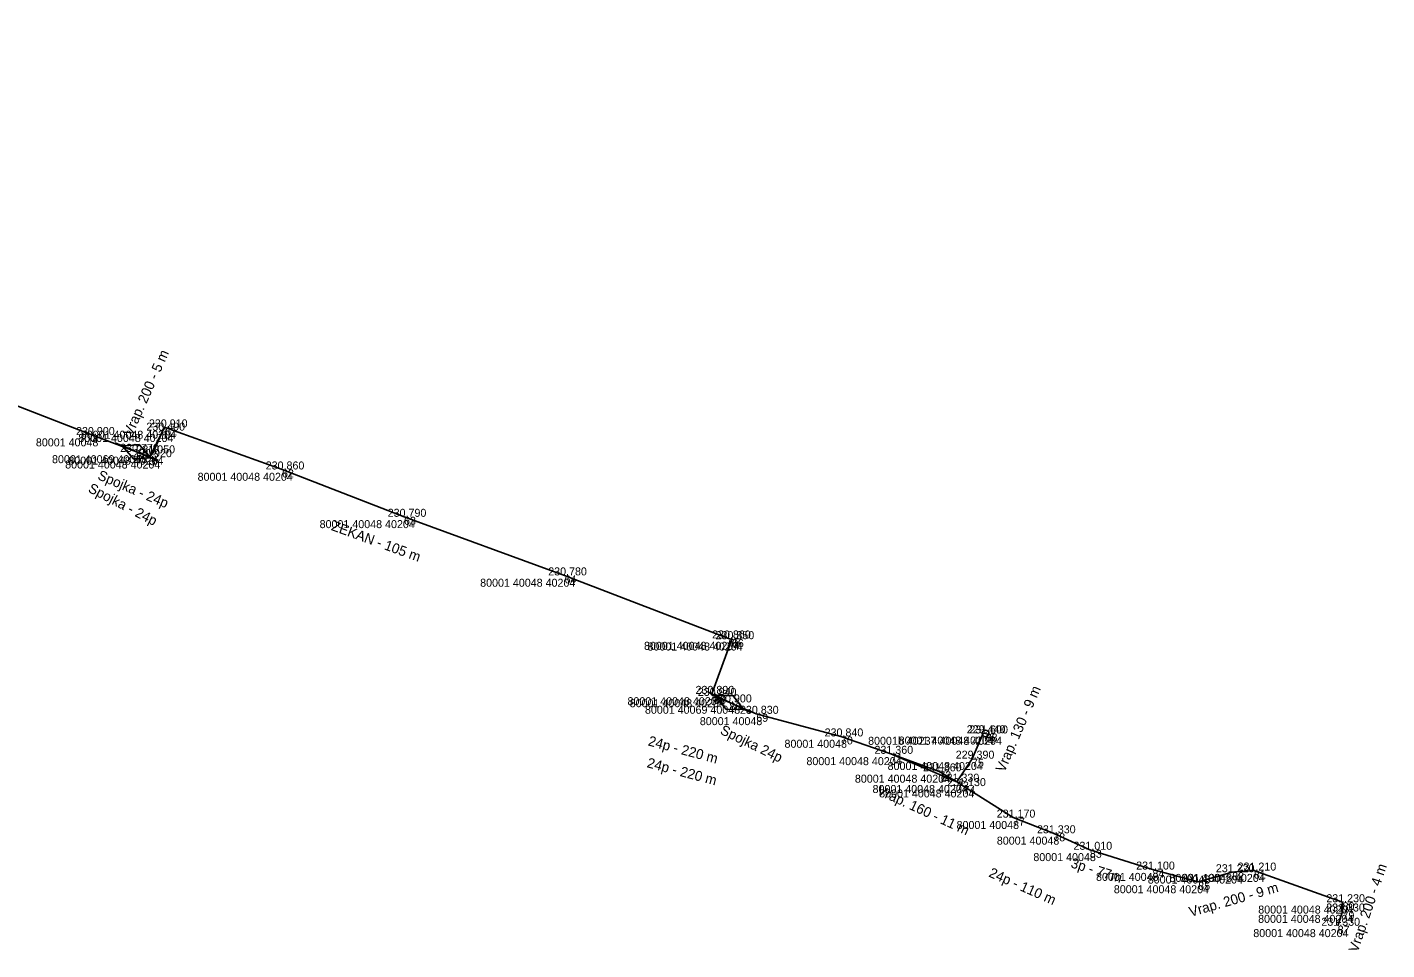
# Model space of a CAD drawing. Extents: x -771675 to -771031, y -1050148 to -1049817.
# Drawn here: x -771234.6 to -771030.6, y -1050147.5 to -1050009.1 of the extents above; entities that cross this region are included whole.
import ezdxf

# ---------------------------------------------------------------- set-up
doc = ezdxf.new("R2010")
doc.units = 0
for name, color, linetype in [('Vrstva 27', 7, 'Continuous'), ('Vrstva 28', 7, 'Continuous'), ('Vrstva 35', 7, 'Continuous'), ('Vrstva 60', 7, 'Continuous'), ('Vrstva 61', 7, 'Continuous'), ('Vrstva 62', 7, 'Continuous')]:
    doc.layers.add(name, color=color, linetype=linetype)

msp = doc.modelspace()

# ---------------------------------------------------------------- linework, layer by layer
at = {"layer": 'Vrstva 27'}
msp.add_line((-771090.85, -1050115.04), (-771090.77, -1050115.1), dxfattribs=at)
msp.add_circle((-771090.81, -1050115.07), 0.5, dxfattribs=at)
at = {"layer": 'Vrstva 28'}
for p, q in [((-771214.92, -1050074.07), (-771221.44, -1050071.59)), ((-771214.92, -1050074.07), (-771221.44, -1050071.59)), ((-771214.97, -1050074.2), (-771221.39, -1050071.46)), ((-771220.35, -1050072), (-771217.77, -1050071.74)), ((-771220.35, -1050072), (-771217.77, -1050071.74)), ((-771218.59, -1050073.92), (-771220.35, -1050072)), ((-771218.59, -1050073.92), (-771220.35, -1050072)), ((-771220.32, -1050071.92), (-771217.72, -1050071.76)), ((-771218.64, -1050073.9), (-771220.32, -1050071.92)), ((-771217.77, -1050071.74), (-771216.01, -1050073.66)), ((-771217.77, -1050071.74), (-771216.01, -1050073.66)), ((-771217.72, -1050071.76), (-771216.04, -1050073.74)), ((-771216.04, -1050073.74), (-771218.64, -1050073.9)), ((-771216.01, -1050073.66), (-771218.59, -1050073.92)), ((-771216.01, -1050073.66), (-771218.59, -1050073.92)), ((-771126.1, -1050111.94), (-771132.38, -1050108.88)), ((-771131.33, -1050109.39), (-771128.73, -1050109.36)), ((-771129.75, -1050111.46), (-771131.33, -1050109.39)), ((-771128.73, -1050109.36), (-771127.15, -1050111.43)), ((-771127.15, -1050111.43), (-771129.75, -1050111.46))]:
    msp.add_line(p, q, dxfattribs=at)
for points in [[(-771381.07, -1050009.14), (-771379.8, -1050009.7), (-771371.17, -1050012.96), (-771358.66, -1050018.45), (-771346.42, -1050023.74), (-771329.39, -1050030.95), (-771327.8, -1050031.37), (-771308.34, -1050039.35), (-771281.13, -1050049.41), (-771278.57, -1050050.27), (-771268.38, -1050053.56), (-771265.96, -1050054.48), (-771239.24, -1050064.74), (-771224.8, -1050070.31), (-771218.18, -1050072.83)], [(-771239.24, -1050064.74), (-771224.8, -1050070.31), (-771218.18, -1050072.83), (-771216.22, -1050073.63), (-771215.75, -1050073.05), (-771214.25, -1050069.65), (-771213.87, -1050069.16), (-771196.35, -1050075.47), (-771178.05, -1050082.57), (-771153.97, -1050091.36), (-771129.39, -1050100.82), (-771128.87, -1050100.93), (-771131.87, -1050109.13), (-771131.54, -1050109.43), (-771129.24, -1050110.41), (-771125.21, -1050112.12), (-771112.51, -1050115.51), (-771105.03, -1050118.12), (-771097.76, -1050120.75), (-771095.11, -1050122.3), (-771094.12, -1050122.96), (-771086.7, -1050127.69), (-771080.66, -1050130.04), (-771075.18, -1050132.51), (-771065.78, -1050135.48), (-771058.92, -1050137.33), (-771053.83, -1050135.88), (-771050.57, -1050135.63), (-771037.26, -1050140.38), (-771037.28, -1050141.77), (-771038, -1050143.91)], [(-771129.24, -1050110.41), (-771131.54, -1050109.43), (-771131.87, -1050109.13), (-771128.87, -1050100.93), (-771129.39, -1050100.82), (-771153.97, -1050091.36), (-771178.05, -1050082.57), (-771196.35, -1050075.47), (-771213.87, -1050069.16), (-771214.25, -1050069.65), (-771215.75, -1050073.05), (-771216.22, -1050073.63), (-771218.18, -1050072.83), (-771224.8, -1050070.31), (-771239.24, -1050064.74)], [(-771218.18, -1050072.83), (-771216.22, -1050073.63), (-771215.75, -1050073.05), (-771214.25, -1050069.65), (-771213.87, -1050069.16), (-771196.35, -1050075.47), (-771178.05, -1050082.57), (-771153.97, -1050091.36), (-771129.39, -1050100.82), (-771128.87, -1050100.93), (-771131.87, -1050109.13), (-771131.54, -1050109.43), (-771129.24, -1050110.41)], [(-771218.18, -1050072.83), (-771216.22, -1050073.63), (-771214.25, -1050069.65), (-771213.87, -1050069.16), (-771196.35, -1050075.47), (-771178.05, -1050082.57), (-771153.97, -1050091.36), (-771129.39, -1050100.82), (-771128.87, -1050100.93), (-771131.87, -1050109.13), (-771131.54, -1050109.43), (-771129.24, -1050110.41), (-771125.21, -1050112.12), (-771112.51, -1050115.51), (-771105.03, -1050118.12), (-771097.76, -1050120.75), (-771095.11, -1050122.3), (-771094.12, -1050122.96), (-771086.7, -1050127.69), (-771080.66, -1050130.04), (-771075.18, -1050132.51), (-771065.78, -1050135.48), (-771058.92, -1050137.33), (-771053.83, -1050135.88), (-771050.57, -1050135.63), (-771037.26, -1050140.38), (-771037.28, -1050141.77), (-771038, -1050143.91)], [(-771038, -1050143.91), (-771037.28, -1050141.77), (-771037.26, -1050140.38), (-771050.57, -1050135.63), (-771053.83, -1050135.88), (-771058.92, -1050137.33), (-771065.78, -1050135.48), (-771075.18, -1050132.51), (-771080.66, -1050130.04), (-771086.7, -1050127.69), (-771094.12, -1050122.96), (-771095.11, -1050122.3), (-771105.03, -1050118.12), (-771112.51, -1050115.51), (-771125.21, -1050112.12), (-771129.24, -1050110.41), (-771131.54, -1050109.43), (-771131.87, -1050109.13), (-771128.87, -1050100.93), (-771129.39, -1050100.82), (-771153.97, -1050091.36), (-771178.05, -1050082.57), (-771196.35, -1050075.47), (-771213.87, -1050069.16), (-771214.25, -1050069.65), (-771215.75, -1050073.05), (-771216.22, -1050073.63), (-771218.18, -1050072.83)], [(-771038, -1050143.91), (-771037.28, -1050141.77), (-771037.26, -1050140.38), (-771050.57, -1050135.63), (-771053.83, -1050135.88), (-771058.92, -1050137.33), (-771065.78, -1050135.48), (-771075.18, -1050132.51), (-771080.66, -1050130.04), (-771086.7, -1050127.69), (-771094.12, -1050122.96), (-771095.11, -1050122.3), (-771097.76, -1050120.75), (-771105.03, -1050118.12), (-771112.51, -1050115.51), (-771125.21, -1050112.12), (-771129.24, -1050110.41)], [(-771038, -1050143.91), (-771037.28, -1050141.77), (-771037.26, -1050140.38), (-771050.57, -1050135.63), (-771053.83, -1050135.88), (-771058.92, -1050137.33), (-771065.78, -1050135.48), (-771075.18, -1050132.51), (-771080.66, -1050130.04), (-771086.7, -1050127.69), (-771094.12, -1050122.96), (-771095.11, -1050122.3), (-771092.85, -1050118.85), (-771091.19, -1050115.03), (-771090.81, -1050115.07)]]:
    msp.add_lwpolyline(points, dxfattribs=at)
at = {"layer": 'Vrstva 35'}
for points in [[(-771213.87, -1050069.16), (-771214.25, -1050069.65), (-771215.75, -1050073.05), (-771216.22, -1050073.63)], [(-771129.39, -1050100.82), (-771153.97, -1050091.36), (-771178.05, -1050082.57), (-771196.35, -1050075.47), (-771213.87, -1050069.16)], [(-771131.54, -1050109.43), (-771131.87, -1050109.13), (-771128.87, -1050100.93), (-771129.39, -1050100.82)], [(-771094.12, -1050122.96), (-771095.11, -1050122.3), (-771092.85, -1050118.85), (-771091.19, -1050115.03), (-771090.81, -1050115.07)], [(-771095.11, -1050122.3), (-771097.76, -1050120.75), (-771105.03, -1050118.12)], [(-771050.57, -1050135.63), (-771053.83, -1050135.88), (-771058.92, -1050137.33)], [(-771038, -1050143.91), (-771037.28, -1050141.77), (-771037.26, -1050140.38)]]:
    msp.add_lwpolyline(points, dxfattribs=at)
at = {"layer": 'Vrstva 60'}
for p, q in [((-771214.25, -1050069.65), (-771214.25, -1050069.65)), ((-771213.87, -1050069.16), (-771213.87, -1050069.16)), ((-771224.8, -1050070.31), (-771224.8, -1050070.31)), ((-771218.18, -1050072.83), (-771218.18, -1050072.83)), ((-771216.22, -1050073.63), (-771216.22, -1050073.63)), ((-771215.75, -1050073.05), (-771215.75, -1050073.05)), ((-771196.35, -1050075.47), (-771196.35, -1050075.47)), ((-771178.05, -1050082.57), (-771178.05, -1050082.57)), ((-771153.97, -1050091.36), (-771153.97, -1050091.36)), ((-771129.39, -1050100.82), (-771129.39, -1050100.82)), ((-771128.87, -1050100.93), (-771128.87, -1050100.93)), ((-771131.87, -1050109.13), (-771131.87, -1050109.13)), ((-771131.54, -1050109.43), (-771131.54, -1050109.43)), ((-771129.24, -1050110.41), (-771129.24, -1050110.41)), ((-771125.21, -1050112.12), (-771125.21, -1050112.12)), ((-771112.51, -1050115.51), (-771112.51, -1050115.51)), ((-771091.19, -1050115.03), (-771091.19, -1050115.03)), ((-771090.81, -1050115.07), (-771090.81, -1050115.07)), ((-771105.03, -1050118.12), (-771105.03, -1050118.12)), ((-771092.85, -1050118.85), (-771092.85, -1050118.85)), ((-771097.76, -1050120.75), (-771097.76, -1050120.75)), ((-771095.11, -1050122.3), (-771095.11, -1050122.3)), ((-771094.12, -1050122.96), (-771094.12, -1050122.96)), ((-771086.7, -1050127.69), (-771086.7, -1050127.69)), ((-771080.66, -1050130.04), (-771080.66, -1050130.04)), ((-771075.18, -1050132.51), (-771075.18, -1050132.51)), ((-771065.78, -1050135.48), (-771065.78, -1050135.48)), ((-771053.83, -1050135.88), (-771053.83, -1050135.88)), ((-771050.57, -1050135.63), (-771050.57, -1050135.63)), ((-771058.92, -1050137.33), (-771058.92, -1050137.33)), ((-771037.26, -1050140.38), (-771037.26, -1050140.38)), ((-771037.28, -1050141.77), (-771037.28, -1050141.77)), ((-771038, -1050143.91), (-771038, -1050143.91))]:
    msp.add_line(p, q, dxfattribs=at)

# ---------------------------------------------------------------- texts
at = {"layer": 'Vrstva 28'}
for s, rotation, p in [('Spojka - 24p', 336.9218, (-771224.14, -1050076.89)), ('Spojka - 24p', 332.5426, (-771225.56, -1050078.77)), ('Spojka 24p', 334.0482, (-771130.76, -1050115.06)), ('24p - 220 m', 345.0545, (-771141.54, -1050116.84)), ('24p - 220 m', 345.0545, (-771141.71, -1050120.11)), ('24p - 110 m', 336.0725, (-771090.46, -1050136.49)), ('3p - 77m', 342.4657, (-771078.15, -1050135.12))]:
    msp.add_text(s, height=1.5, rotation=rotation, dxfattribs=at).set_placement(p)
at = {"layer": 'Vrstva 35'}
for s, rotation, p in [('Vrap. 200 - 5 m', 66.1941, (-771218.85, -1050070.59)), ('ZEKAN - 105 m', 339.9462, (-771189.08, -1050084.53)), ('Vrap. 130 - 9 m', 66.5124, (-771088, -1050121)), ('Vrap. 160 - 11 m', 335.2724, (-771107.26, -1050124.12)), ('Vrap. 200 - 4 m', 71.4046, (-771035, -1050148)), ('Vrap. 200 - 9 m', 15.9008, (-771060.06, -1050142.58))]:
    msp.add_text(s, height=1.5, rotation=rotation, dxfattribs=at).set_placement(p)
at = {"layer": 'Vrstva 60'}
for s, p in [('1', (-771214.25, -1050070.85)), ('61', (-771213.87, -1050070.36)), ('4', (-771224.8, -1050071.51)), ('60', (-771218.18, -1050074.03)), ('3', (-771216.22, -1050074.83)), ('2', (-771215.75, -1050074.25)), ('62', (-771196.35, -1050076.67)), ('63', (-771178.05, -1050083.77)), ('64', (-771153.97, -1050092.56)), ('65', (-771129.39, -1050102.02)), ('66', (-771128.87, -1050102.13)), ('67', (-771131.87, -1050110.33)), ('68', (-771131.54, -1050110.63)), ('86', (-771129.24, -1050111.61)), ('69', (-771125.21, -1050113.32)), ('70', (-771112.51, -1050116.71)), ('76', (-771091.19, -1050116.23)), ('88', (-771090.81, -1050116.27)), ('71', (-771105.03, -1050119.32)), ('75', (-771092.85, -1050120.05)), ('72', (-771097.76, -1050121.95)), ('73', (-771095.11, -1050123.5)), ('74', (-771094.12, -1050124.16)), ('77', (-771086.7, -1050128.89)), ('78', (-771080.66, -1050131.24)), ('83', (-771075.18, -1050133.71)), ('84', (-771065.78, -1050136.68)), ('82', (-771053.83, -1050137.08)), ('81', (-771050.57, -1050136.83)), ('85', (-771058.92, -1050138.53)), ('80', (-771037.26, -1050141.58)), ('79', (-771037.28, -1050142.97)), ('87', (-771038, -1050145.11))]:
    msp.add_text(s, height=1.2, dxfattribs=at).set_placement(p)
at = {"layer": 'Vrstva 61'}
for s, p in [('230.910', (-771216.32, -1050069.16)), ('230.900', (-771227.25, -1050070.31)), ('230.490', (-771216.7, -1050069.65)), ('230.770', (-771220.63, -1050072.83)), ('231.050', (-771218.2, -1050073.05)), ('230.920', (-771218.67, -1050073.63)), ('230.860', (-771198.8, -1050075.47)), ('230.790', (-771180.5, -1050082.57)), ('230.780', (-771156.42, -1050091.36)), ('230.860', (-771131.84, -1050100.82)), ('230.850', (-771131.32, -1050100.93)), ('230.890', (-771134.32, -1050109.13)), ('230.940', (-771133.99, -1050109.43)), ('230.900', (-771131.69, -1050110.41)), ('230.830', (-771127.66, -1050112.12)), ('230.840', (-771114.96, -1050115.51)), ('229.440', (-771093.64, -1050115.03)), ('231.600', (-771093.26, -1050115.07)), ('231.360', (-771107.48, -1050118.12)), ('229.390', (-771095.3, -1050118.85)), ('231.360', (-771100.21, -1050120.75)), ('231.330', (-771097.56, -1050122.3)), ('231.130', (-771096.57, -1050122.96)), ('231.170', (-771089.15, -1050127.69)), ('231.330', (-771083.11, -1050130.04)), ('231.010', (-771077.63, -1050132.51)), ('231.100', (-771068.23, -1050135.48)), ('231.220', (-771056.28, -1050135.88)), ('231.210', (-771053.02, -1050135.63)), ('231.130', (-771061.37, -1050137.33)), ('231.230', (-771039.71, -1050140.38)), ('231.330', (-771039.73, -1050141.77)), ('231.330', (-771040.45, -1050143.91))]:
    msp.add_text(s, height=1.2, dxfattribs=at).set_placement(p)
at = {"layer": 'Vrstva 62'}
for s, p in [('80001 40048 40204', (-771226.53, -1050070.86)), ('80001 40048', (-771233.27, -1050072.01)), ('80001 40048 40204', (-771226.91, -1050071.35)), ('80001 40069 40048', (-771230.85, -1050074.53)), ('80001 40048 40204', (-771228.41, -1050074.75)), ('80001 40048 40204', (-771228.88, -1050075.33)), ('80001 40048 40204', (-771209.01, -1050077.17)), ('80001 40048 40204', (-771190.71, -1050084.27)), ('80001 40048 40204', (-771166.63, -1050093.06)), ('80001 40048 40204', (-771142.05, -1050102.52)), ('80001 40048 40204', (-771141.53, -1050102.63)), ('80001 40048 40204', (-771144.53, -1050110.83)), ('80001 40048 40204', (-771144.2, -1050111.13)), ('80001 40069 40048', (-771141.91, -1050112.11)), ('80001 40048', (-771133.68, -1050113.82)), ('80001 40048', (-771120.98, -1050117.21)), ('80001b 40237 40048 40204', (-771108.44, -1050116.77)), ('80001 40048 40204', (-771103.85, -1050116.73)), ('80001 40048 40204', (-771117.69, -1050119.82)), ('80001 40048 40204', (-771105.51, -1050120.55)), ('80001 40048 40204', (-771110.42, -1050122.45)), ('80001 40048 40204', (-771107.77, -1050124)), ('80001 40048 40204', (-771106.78, -1050124.66)), ('80001 40048', (-771095.17, -1050129.39)), ('80001 40048', (-771089.13, -1050131.74)), ('80001 40048', (-771083.65, -1050134.21)), ('80001 40048', (-771074.25, -1050137.18)), ('80001 40048 40204', (-771066.49, -1050137.58)), ('80001 40048 40204', (-771063.23, -1050137.33)), ('80001 40048 40204', (-771071.58, -1050139.03)), ('80001 40048 40204', (-771049.92, -1050142.08)), ('80001 40048 40204', (-771049.94, -1050143.47)), ('80001 40048 40204', (-771050.66, -1050145.61))]:
    msp.add_text(s, height=1.2, dxfattribs=at).set_placement(p)

doc.saveas('drawing.dxf')
